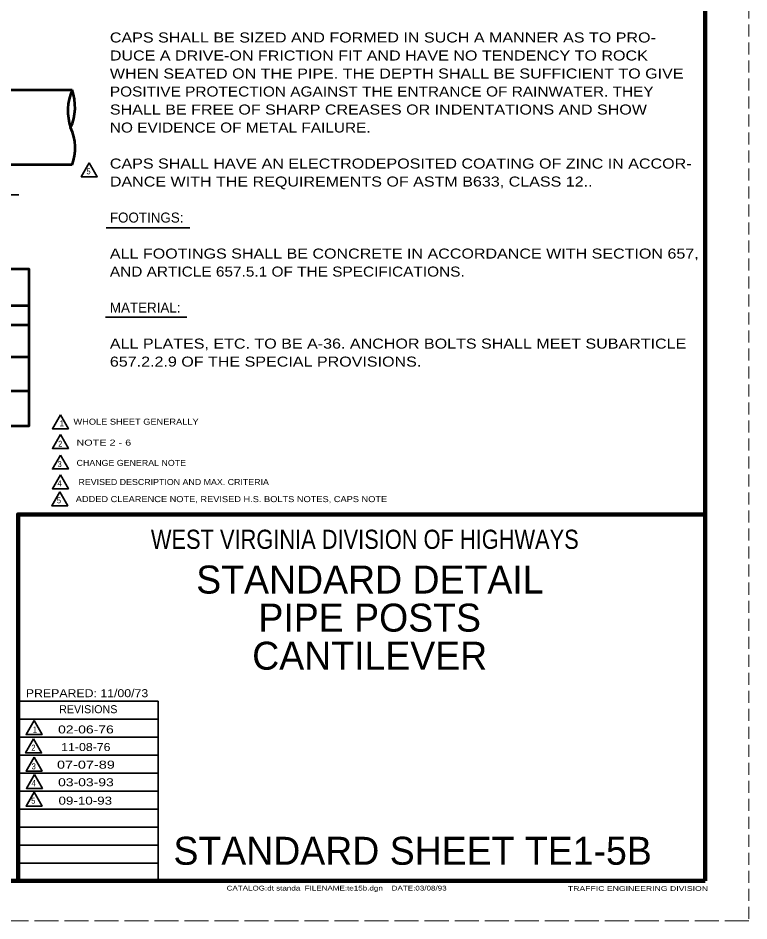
# Model space of a CAD drawing. Extents: x -209 to 471, y -242 to 199.
# Drawn here: x 288.8 to 471.4, y -241.5 to -15.9 of the extents above; entities that cross this region are included whole.
import ezdxf
from ezdxf.enums import TextEntityAlignment as Align

# ---------------------------------------------------------------- set-up
doc = ezdxf.new("R2010")
doc.units = 0
doc.linetypes.add('LONG_DASHED', pattern=[7.5, 6, -1.5])
doc.linetypes.add('MEDIUM_DASHED', pattern=[4.5, 3, -1.5])
doc.layers.add('1', color=7, linetype='Continuous', lineweight=53)
doc.layers.add('61', color=7, linetype='Continuous', lineweight=35)

msp = doc.modelspace()

# ---------------------------------------------------------------- linework, layer by layer
at = {"layer": '1', "linetype": 'MEDIUM_DASHED', "lineweight": 13}
msp.add_line((471.374, 198.515), (471.354, -241.505), dxfattribs=at)
at = {"layer": '1'}
for p, q in [((274.305, -33.803), (302.263, -33.803)), ((302.263, -52.595), (274.305, -52.595)), ((161.937, -87.683), (291.427, -87.683)), ((148.383, -92.583), (291.427, -92.583)), ((148.383, -100.586), (291.427, -100.586)), ((148.383, -109.08), (291.427, -109.08))]:
    msp.add_line(p, q, dxfattribs=at)
at = {"layer": '1', "lineweight": 35}
for p, q in [((310.802, -68.268), (331.693, -68.268)), ((310.637, -90.599), (330.911, -90.599)), ((323.754, -191.085), (288.774, -191.085)), ((323.754, -195.585), (288.774, -195.585)), ((323.754, -200.085), (288.774, -200.085)), ((323.754, -204.605), (288.774, -204.605)), ((323.754, -209.085), (288.774, -209.085)), ((323.754, -213.565), (288.774, -213.565)), ((323.754, -218.065), (288.774, -218.065)), ((323.754, -222.565), (288.774, -222.565)), ((323.754, -227.085), (288.774, -227.085))]:
    msp.add_line(p, q, dxfattribs=at)
for points in [[(273.637, -53.231), (279.159, -60.088), (288.933, -60.088)], [(323.754, -231.565), (323.754, -186.605), (288.774, -186.605)]]:
    msp.add_lwpolyline(points, dxfattribs=at)
for points in [[(306.563, -52.093), (304.563, -55.557), (308.563, -55.557)], [(299.345, -115.043), (297.345, -118.507), (301.345, -118.507)], [(299.345, -119.985), (297.345, -123.449), (301.345, -123.449)], [(299.345, -125.091), (297.345, -128.555), (301.345, -128.555)], [(299.345, -130.033), (297.345, -133.497), (301.345, -133.497)], [(299.167, -134.312), (297.167, -137.776), (301.167, -137.776)], [(292.772, -191.473), (290.772, -194.937), (294.772, -194.937)], [(292.642, -196.054), (290.642, -199.518), (294.642, -199.518)], [(292.768, -200.607), (290.768, -204.071), (294.768, -204.071)], [(292.835, -204.949), (290.835, -208.413), (294.835, -208.413)], [(292.751, -209.369), (290.751, -212.833), (294.751, -212.833)]]:
    msp.add_lwpolyline(points, close=True, dxfattribs=at)
at = {"layer": '1'}
msp.add_lwpolyline([(148.383, -78.587), (291.427, -78.587), (291.427, -117.853), (148.383, -117.853)], close=True, dxfattribs=at)
at = {"layer": '1', "lineweight": 158}
msp.add_lwpolyline([(288.754, -231.525), (288.754, -139.945), (460.414, -139.945)], dxfattribs=at)
at = {"layer": '1'}
for centre, radius, start, end in [((314.683, -39.035), 13.476, 157.15502, 198.32981), ((290.443, -38.079), 12.57, 335.59533, 19.88949), ((291.148, -48.372), 11.891, 339.19717, 25.38978)]:
    msp.add_arc(centre, radius, start, end, dxfattribs=at)
at = {"layer": '61', "lineweight": 158}
for p, q in [((460.394, 188.515), (460.414, -231.525)), ((460.414, -231.525), (-178.646, -231.505))]:
    msp.add_line(p, q, dxfattribs=at)
at = {"layer": '61', "linetype": 'LONG_DASHED', "lineweight": 13}
msp.add_line((471.354, -241.505), (-208.706, -241.525), dxfattribs=at)

# ---------------------------------------------------------------- texts
at = {"layer": '1'}
for s, height, width, p in [('CAPS SHALL BE SIZED AND FORMED IN SUCH A MANNER AS TO PRO-', 2.5, 1.2, (311.706, -21.989)), ('DUCE A DRIVE-ON FRICTION FIT AND HAVE NO TENDENCY TO ROCK', 2.5, 1.2, (311.706, -26.489)), ('WHEN SEATED ON THE PIPE. THE DEPTH SHALL BE SUFFICIENT TO GIVE', 2.5, 1.2, (311.706, -30.989)), ('POSITIVE PROTECTION AGAINST THE ENTRANCE OF RAINWATER. THEY', 2.5, 1.15, (311.706, -35.489)), ('SHALL BE FREE OF SHARP CREASES OR INDENTATIONS AND SHOW', 2.5, 1.2, (311.706, -39.989)), ('NO EVIDENCE OF METAL FAILURE.', 2.5, 1.15, (311.706, -44.489)), ('CAPS SHALL HAVE AN ELECTRODEPOSITED COATING OF ZINC IN ACCOR-', 2.5, 1.2, (311.706, -53.489)), ('DANCE WITH THE REQUIREMENTS OF ASTM B633, CLASS 12..', 2.5, 1.2, (311.706, -57.989)), ('ALL FOOTINGS SHALL BE CONCRETE IN ACCORDANCE WITH SECTION 657,', 2.5, 1.2, (311.706, -75.989)), ('AND ARTICLE 657.5.1 OF THE SPECIFICATIONS.', 2.5, 1.15, (311.706, -80.489)), ('ALL PLATES, ETC. TO BE A-36. ANCHOR BOLTS SHALL MEET SUBARTICLE', 2.5, 1.2, (311.706, -98.489)), ('657.2.2.9 OF THE SPECIAL PROVISIONS.', 2.5, 1.2, (311.706, -102.989)), ('PREPARED: 11/00/73', 1.998, 1.15, (290.714, -185.605)), ('CATALOG:dt standa  FILENAME:te15b.dgn    DATE:03/08/93', 1.2, 1.25, (340.874, -233.925)), ('TRAFFIC ENGINEERING DIVISION', 1.2, 1.35, (426.134, -234.025))]:
    msp.add_text(s, height=height, dxfattribs=dict(at, width=width)).set_placement(p)
for s, height, width, p in [('5', 1.5, 0.9, (306.37, -54.937)), ('WHOLE SHEET GENERALLY', 1.5, 1.15, (318.25, -117.504)), ('2', 1.5, 0.9, (299.301, -123.026)), ('NOTE 2 - 6', 1.5, 1.35, (310.193, -122.728)), ('CHANGE GENERAL NOTE', 1.5, 1.1, (317.057, -127.802)), ('3', 1.5, 0.9, (299.152, -128.101)), ('4', 1.5, 0.95, (299.152, -132.877)), ('REVISED DESCRIPTION AND MAX. CRITERIA', 1.5, 1.1, (327.65, -132.579)), ('ADDED CLEARENCE NOTE, REVISED H.S. BOLTS NOTES, CAPS NOTE', 1.5, 1.15, (342.086, -136.857)), ('5', 1.5, 0.9, (298.974, -137.156)), ('WEST VIRGINIA DIVISION OF HIGHWAYS', 4.795, 0.85, (375.402, -148.545)), ('02-06-76', 2, 1.3, (305.723, -194.665)), ('2', 1.5, 0.9, (292.606, -198.975)), ('11-08-76', 2, 1.15, (305.703, -199.065)), ('3', 1.5, 0.9, (292.673, -203.642)), ('07-07-89', 2, 1.35, (305.723, -203.465)), ('4', 1.5, 0.95, (292.673, -207.843)), ('03-03-93', 2, 1.3, (305.723, -207.865)), ('5', 1.5, 0.9, (292.558, -212.213)), ('09-10-93', 2, 1.25, (305.563, -212.465))]:
    msp.add_text(s, height=height, dxfattribs=dict(at, width=width)).set_placement(p, align=Align.CENTER)
for s, height, p in [('FOOTINGS:', 2.5, (311.706, -66.989)), ('MATERIAL:', 2.5, (311.706, -89.489)), ('REVISIONS', 1.998, (299.034, -189.605)), ('STANDARD SHEET TE1-5B', 6.993, (327.594, -227.485))]:
    msp.add_text(s, height=height, dxfattribs=at).set_placement(p)
for s, height, p in [('1', 1.5, (299.687, -117.952)), ('STANDARD DETAIL', 6.993, (376.671, -159.705)), ('PIPE POSTS', 6.993, (376.624, -169.221)), ('CANTILEVER', 6.993, (376.624, -178.737)), ('1', 1.5, (292.992, -194.442))]:
    msp.add_text(s, height=height, dxfattribs=at).set_placement(p, align=Align.CENTER)

doc.saveas('drawing.dxf')
